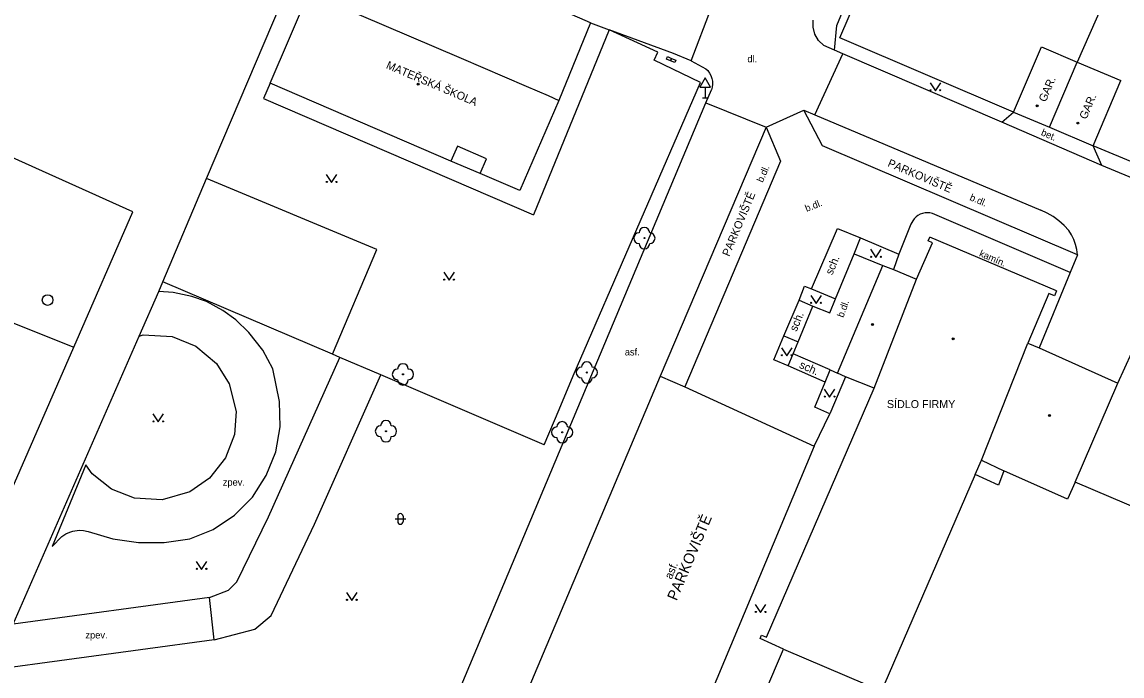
# Model space of a CAD drawing. Extents: x -596024 to -594475, y -1163820 to -1161957.
# Drawn here: x -594676 to -594573, y -1162370.7 to -1162309.5 of the extents above; entities that cross this region are included whole.
import ezdxf

# ---------------------------------------------------------------- set-up
doc = ezdxf.new("R2010")
doc.units = 0
for name, color, linetype in [('Level 10', 7, 'Continuous'), ('Level 11', 7, 'Continuous'), ('Level 22', 7, 'Continuous'), ('Level 24', 7, 'Continuous'), ('Level 27', 7, 'Continuous'), ('Level 34', 7, 'Continuous'), ('Level 36', 7, 'Continuous'), ('Level 39', 7, 'Continuous'), ('Level 40', 7, 'Continuous'), ('Level 41', 7, 'Continuous'), ('Level 5', 7, 'Continuous'), ('Level 7', 7, 'Continuous'), ('Level 8', 7, 'Continuous')]:
    doc.layers.add(name, color=color, linetype=linetype)

msp = doc.modelspace()

# ---------------------------------------------------------------- linework, layer by layer
at = {"layer": 'Level 10'}
for points in [[(-594622.76, -1162309.54), (-594647.87, -1162298.54)], [(-594600.91, -1162311.66), (-594601.39, -1162311.19), (-594601.73, -1162310.61), (-594601.9, -1162309.95), (-594601.89, -1162309.28)], [(-594613.33, -1162313.08), (-594614.98, -1162312.42), (-594621.02, -1162310.19)], [(-594599.91, -1162312.1), (-594600.91, -1162311.66)], [(-594599.12, -1162312.45), (-594599.91, -1162312.1)], [(-594613.33, -1162313.08), (-594611.96, -1162313.83)], [(-594584.21, -1162318.84), (-594599.12, -1162312.45)], [(-594611.96, -1162313.83), (-594611.78, -1162314.01), (-594611.61, -1162314.24), (-594611.49, -1162314.46), (-594611.39, -1162314.74), (-594611.34, -1162315.01), (-594611.32, -1162315.28), (-594611.35, -1162315.56), (-594611.42, -1162315.82)], [(-594611.94, -1162317.04), (-594611.42, -1162315.82)], [(-594642.05, -1162388.75), (-594611.94, -1162317.04)], [(-594606.29, -1162319.32), (-594602.76, -1162317.71)], [(-594577.13, -1162331.25), (-594601.01, -1162321.06), (-594602.76, -1162317.71)], [(-594606.29, -1162319.32), (-594604.95, -1162322.49)], [(-594574.87, -1162322.9), (-594584.21, -1162318.84)], [(-594604.95, -1162322.49), (-594613.93, -1162343.63)], [(-594539.21, -1162337.87), (-594548.12, -1162333.98), (-594574.87, -1162322.9)], [(-594577.13, -1162331.25), (-594577.82, -1162332.91)], [(-594577.82, -1162332.91), (-594580.74, -1162339.99)], [(-594613.93, -1162343.63), (-594601.79, -1162349.18)], [(-594601.79, -1162349.18), (-594613.48, -1162377.11), (-594617.98, -1162375.35)]]:
    msp.add_lwpolyline(points, dxfattribs=at)
at = {"layer": 'Level 11'}
for points in [[(-594599.91, -1162312.1), (-594599.68, -1162309.78), (-594594.58, -1162297.5), (-594588.31, -1162282.81)], [(-594687.26, -1162376.68), (-594671.17, -1162339.92), (-594665.63, -1162327.25), (-594696.11, -1162313.53), (-594685.6, -1162289.88), (-594682.8, -1162283.58)], [(-594573.15, -1162304.08), (-594577.17, -1162313.21)], [(-594613.33, -1162313.08), (-594611.41, -1162308.1)], [(-594621.02, -1162310.19), (-594628.11, -1162327.52)], [(-594601.73, -1162318.15), (-594599.12, -1162312.45)], [(-594652.78, -1162315.18), (-594653.4, -1162316.62), (-594628.11, -1162327.52)], [(-594611.94, -1162317.04), (-594606.29, -1162319.32)], [(-594602.76, -1162317.71), (-594601.73, -1162318.15)], [(-594601.73, -1162318.15), (-594580.56, -1162327.08)], [(-594584.21, -1162318.84), (-594583.12, -1162317.89)], [(-594606.29, -1162319.32), (-594616.22, -1162342.62)], [(-594574.87, -1162322.9), (-594575.66, -1162321.06)], [(-594646.93, -1162340.58), (-594642.78, -1162330.76), (-594658.72, -1162324.12)], [(-594590.73, -1162327.4), (-594590.96, -1162327.34), (-594591.19, -1162327.32), (-594591.42, -1162327.34), (-594591.65, -1162327.38), (-594591.87, -1162327.46), (-594592.08, -1162327.58), (-594592.26, -1162327.72), (-594592.43, -1162327.88), (-594592.56, -1162328.07)], [(-594577.82, -1162332.91), (-594590.73, -1162327.4)], [(-594577.13, -1162331.25), (-594577.2, -1162330.77), (-594577.31, -1162330.3), (-594577.48, -1162329.84), (-594577.69, -1162329.4), (-594577.94, -1162328.98), (-594578.39, -1162328.51), (-594578.88, -1162328.08), (-594579.41, -1162327.69), (-594579.97, -1162327.36), (-594580.56, -1162327.08)], [(-594592.76, -1162328.39), (-594593.86, -1162331.19)], [(-594592.56, -1162328.07), (-594592.76, -1162328.39)], [(-594602.06, -1162334.46), (-594599.61, -1162328.79), (-594597.47, -1162329.68)], [(-594598.07, -1162331.16), (-594597.47, -1162329.68)], [(-594597.47, -1162329.68), (-594593.86, -1162331.19)], [(-594599.81, -1162335.4), (-594598.07, -1162331.16)], [(-594598.07, -1162331.16), (-594595.37, -1162332.25)], [(-594593.86, -1162331.19), (-594594.38, -1162332.65)], [(-594652.53, -1162341.95), (-594653.47, -1162340.19), (-594654.76, -1162338.55), (-594656, -1162337.36), (-594657.22, -1162336.49), (-594658.75, -1162335.65), (-594660.1, -1162335.17), (-594661.86, -1162334.8), (-594663.21, -1162334.69)], [(-594603.22, -1162335.52), (-594602.7, -1162334.2), (-594602.06, -1162334.46)], [(-594602.06, -1162334.46), (-594599.81, -1162335.4)], [(-594604.64, -1162338.85), (-594603.22, -1162335.52)], [(-594603.31, -1162339.41), (-594601.92, -1162336.07), (-594600.35, -1162336.71), (-594599.81, -1162335.4)], [(-594603.22, -1162335.52), (-594601.92, -1162336.07)], [(-594677.49, -1162337.37), (-594671.17, -1162339.92)], [(-594664.67, -1162338.77), (-594661.94, -1162338.92), (-594659.74, -1162339.81), (-594657.81, -1162341.43), (-594656.6, -1162343.35), (-594655.96, -1162345.95), (-594656.11, -1162348.09), (-594656.94, -1162350.28), (-594658.45, -1162352.2), (-594660.31, -1162353.47), (-594662.88, -1162354.22), (-594665.48, -1162354.07), (-594667.64, -1162353.22), (-594669.44, -1162351.78), (-594670.03, -1162350.95)], [(-594665.04, -1162338.87), (-594664.67, -1162338.77)], [(-594604.23, -1162341.67), (-594605.58, -1162341.11), (-594604.64, -1162338.85)], [(-594604.64, -1162338.85), (-594603.31, -1162339.41)], [(-594600.32, -1162342.05), (-594603.77, -1162340.53), (-594603.31, -1162339.41)], [(-594658.45, -1162363.35), (-594656.66, -1162362.68), (-594655.9, -1162361.91), (-594652.94, -1162355.82), (-594646.25, -1162340.87)], [(-594604.23, -1162341.67), (-594603.77, -1162340.53)], [(-594660.31, -1162357.88), (-594658.1, -1162356.98), (-594656.12, -1162355.65), (-594654.44, -1162353.95), (-594653.13, -1162351.95), (-594652.25, -1162349.73), (-594651.83, -1162347.38), (-594651.89, -1162345), (-594652.53, -1162341.95)], [(-594600.76, -1162343.19), (-594604.23, -1162341.67)], [(-594600.34, -1162346.17), (-594601.74, -1162345.54), (-594600.76, -1162343.19), (-594600.32, -1162342.05)], [(-594600.32, -1162342.05), (-594599.63, -1162342.34)], [(-594658.03, -1162367.34), (-594654.21, -1162366.32), (-594652.68, -1162365.05), (-594648.62, -1162356.49), (-594642.39, -1162342.52)], [(-594616.22, -1162342.62), (-594629.13, -1162373.21)], [(-594616.22, -1162342.62), (-594613.93, -1162343.63)], [(-594598.88, -1162342.69), (-594600.34, -1162346.17)], [(-594601.79, -1162349.18), (-594600.34, -1162346.17)], [(-594670.03, -1162350.95), (-594673.18, -1162358.58)], [(-594586.14, -1162350.51), (-594584.04, -1162351.49)], [(-594673.18, -1162358.58), (-594672.28, -1162357.64), (-594671.92, -1162357.41), (-594671.53, -1162357.23), (-594671.26, -1162357.15), (-594670.68, -1162357.07), (-594670.25, -1162357.09), (-594669.83, -1162357.18)], [(-594669.83, -1162357.18), (-594667.51, -1162357.86), (-594665.12, -1162358.21), (-594662.7, -1162358.22), (-594660.31, -1162357.88)], [(-594658.45, -1162363.35), (-594676.86, -1162365.85)], [(-594658.03, -1162367.34), (-594658.45, -1162363.35)], [(-594658.03, -1162367.34), (-594678.74, -1162370.15)]]:
    msp.add_lwpolyline(points, dxfattribs=at)
at = {"layer": 'Level 22'}
for centre in [(-594617.71, -1162329.7), (-594640.33, -1162342.46), (-594623.1, -1162342.29), (-594641.92, -1162347.79), (-594625.41, -1162347.89)]:
    msp.add_circle(centre, 0.05, dxfattribs=at)
for centre, start, end in [((-594618.21, -1162329.7), 90, 270), ((-594617.71, -1162329.2), 0, 180), ((-594617.21, -1162329.7), 270, 90), ((-594617.71, -1162330.2), 180, 0), ((-594640.83, -1162342.46), 90, 270), ((-594640.33, -1162341.96), 0, 180), ((-594639.83, -1162342.46), 270, 90), ((-594623.6, -1162342.29), 90, 270), ((-594623.1, -1162341.79), 0, 180), ((-594622.6, -1162342.29), 270, 90), ((-594640.33, -1162342.96), 180, 0), ((-594623.1, -1162342.79), 180, 0), ((-594641.92, -1162347.29), 0, 180), ((-594625.41, -1162347.39), 0, 180), ((-594642.42, -1162347.79), 90, 270), ((-594641.42, -1162347.79), 270, 90), ((-594625.91, -1162347.89), 90, 270), ((-594624.91, -1162347.89), 270, 90), ((-594641.92, -1162348.29), 180, 0), ((-594625.41, -1162348.39), 180, 0)]:
    msp.add_arc(centre, 0.5, start, end, dxfattribs=at)
at = {"layer": 'Level 24'}
for points in [[(-594615.56, -1162312.7), (-594615.18, -1162312.86), (-594615.27, -1162313.1), (-594615.65, -1162312.94), (-594615.56, -1162312.7)], [(-594615.18, -1162312.86), (-594614.76, -1162313.03), (-594614.86, -1162313.26), (-594615.27, -1162313.1), (-594615.18, -1162312.86)]]:
    msp.add_lwpolyline(points, dxfattribs=at)
at = {"layer": 'Level 27'}
msp.add_circle((-594673.62, -1162335.5), 0.5, dxfattribs=at)
at = {"layer": 'Level 34'}
for p, q in [((-594612.03, -1162315.55), (-594612.03, -1162316.57)), ((-594612.28, -1162316.57), (-594611.78, -1162316.57))]:
    msp.add_line(p, q, dxfattribs=at)
msp.add_lwpolyline([(-594612.53, -1162315.55), (-594611.53, -1162315.55), (-594612.03, -1162314.69)], close=True, dxfattribs=at)
at = {"layer": 'Level 36'}
for p, q in [((-594641.07, -1162356), (-594640.07, -1162356)), ((-594640.82, -1162355.75), (-594640.82, -1162356.25)), ((-594640.32, -1162355.75), (-594640.32, -1162356.25))]:
    msp.add_line(p, q, dxfattribs=at)
for points in [[(-594590.95, -1162315.15), (-594590.45, -1162315.9), (-594589.95, -1162315.15)], [(-594647.51, -1162323.74), (-594647.01, -1162324.49), (-594646.51, -1162323.74)], [(-594596.52, -1162330.75), (-594596.02, -1162331.5), (-594595.52, -1162330.75)], [(-594636.51, -1162332.89), (-594636.01, -1162333.64), (-594635.51, -1162332.89)], [(-594602.13, -1162335.06), (-594601.63, -1162335.81), (-594601.13, -1162335.06)], [(-594604.88, -1162339.97), (-594604.38, -1162340.72), (-594603.88, -1162339.97)], [(-594600.86, -1162343.84), (-594600.36, -1162344.59), (-594599.86, -1162343.84)], [(-594663.75, -1162346.17), (-594663.25, -1162346.92), (-594662.75, -1162346.17)], [(-594659.7, -1162359.98), (-594659.2, -1162360.73), (-594658.7, -1162359.98)], [(-594645.62, -1162362.88), (-594645.12, -1162363.63), (-594644.62, -1162362.88)], [(-594607.32, -1162364.02), (-594606.82, -1162364.77), (-594606.32, -1162364.02)]]:
    msp.add_lwpolyline(points, dxfattribs=at)
for centre in [(-594590.9, -1162315.85), (-594590, -1162315.85), (-594647.46, -1162324.44), (-594646.56, -1162324.44), (-594596.47, -1162331.45), (-594595.57, -1162331.45), (-594636.46, -1162333.59), (-594635.56, -1162333.59), (-594602.08, -1162335.76), (-594601.18, -1162335.76), (-594604.83, -1162340.67), (-594603.93, -1162340.67), (-594600.81, -1162344.54), (-594599.91, -1162344.54), (-594663.7, -1162346.87), (-594662.8, -1162346.87), (-594659.65, -1162360.68), (-594658.75, -1162360.68), (-594645.57, -1162363.58), (-594644.67, -1162363.58), (-594607.27, -1162364.72), (-594606.37, -1162364.72)]:
    msp.add_circle(centre, 0.05, dxfattribs=at)
for centre, start, end in [((-594640.57, -1162355.75), 0, 180), ((-594640.57, -1162356.25), 180, 0)]:
    msp.add_arc(centre, 0.25, start, end, dxfattribs=at)
at = {"layer": 'Level 39'}
for centre, radius in [((-594638.91, -1162315.27), 0.09), ((-594638.91, -1162315.27), 0.0398), ((-594580.92, -1162317.3), 0.09), ((-594580.92, -1162317.3), 0.0398), ((-594577.11, -1162318.92), 0.09), ((-594577.11, -1162318.92), 0.0398), ((-594596.34, -1162337.79), 0.09), ((-594596.34, -1162337.79), 0.0398), ((-594588.78, -1162339.14), 0.09), ((-594588.78, -1162339.14), 0.0398), ((-594579.77, -1162346.31), 0.09), ((-594579.77, -1162346.31), 0.0398)]:
    msp.add_circle(centre, radius, dxfattribs=at)
at = {"layer": 'Level 5'}
for points in [[(-594652.78, -1162315.18), (-594649.14, -1162306.71)], [(-594649.14, -1162306.71), (-594634.89, -1162312.85)], [(-594583.12, -1162317.89), (-594580.52, -1162311.78)], [(-594580.52, -1162311.78), (-594577.17, -1162313.21)], [(-594634.89, -1162312.85), (-594628.79, -1162315.47)], [(-594579.76, -1162319.32), (-594577.17, -1162313.21)], [(-594577.17, -1162313.21), (-594573.06, -1162314.95)], [(-594635.83, -1162322.48), (-594652.78, -1162315.18)], [(-594575.66, -1162321.06), (-594573.06, -1162314.95)], [(-594628.79, -1162315.47), (-594626.74, -1162316.33)], [(-594625.73, -1162316.8), (-594629.39, -1162325.25)], [(-594626.74, -1162316.33), (-594625.73, -1162316.8)], [(-594583.12, -1162317.89), (-594579.76, -1162319.32)], [(-594579.76, -1162319.32), (-594575.66, -1162321.06)], [(-594635.23, -1162321.08), (-594635.83, -1162322.48)], [(-594632.49, -1162322.26), (-594635.23, -1162321.08)], [(-594633.09, -1162323.66), (-594635.83, -1162322.48)], [(-594633.09, -1162323.66), (-594632.49, -1162322.26)], [(-594629.39, -1162325.25), (-594633.09, -1162323.66)], [(-594591.12, -1162329.96), (-594590.96, -1162329.6)], [(-594579.09, -1162334.65), (-594590.96, -1162329.6)], [(-594592.23, -1162333.53), (-594590.73, -1162330.13)], [(-594590.73, -1162330.13), (-594591.12, -1162329.96)], [(-594599.63, -1162342.34), (-594595.37, -1162332.25)], [(-594595.37, -1162332.25), (-594594.38, -1162332.65), (-594592.23, -1162333.53)], [(-594596.19, -1162343.77), (-594592.23, -1162333.53)], [(-594579.09, -1162334.65), (-594579.29, -1162335.11)], [(-594579.81, -1162334.89), (-594581.78, -1162339.53)], [(-594579.29, -1162335.11), (-594579.81, -1162334.89)], [(-594586.14, -1162350.51), (-594581.78, -1162339.53)], [(-594581.78, -1162339.53), (-594580.74, -1162339.99)], [(-594580.74, -1162339.99), (-594573.35, -1162343.29)], [(-594573.35, -1162343.29), (-594572.06, -1162340.42)], [(-594598.88, -1162342.69), (-594599.63, -1162342.34)], [(-594596.19, -1162343.77), (-594598.88, -1162342.69)], [(-594606.28, -1162367.08), (-594596.19, -1162343.77)], [(-594577.36, -1162352.56), (-594573.35, -1162343.29)], [(-594586.71, -1162351.83), (-594586.14, -1162350.51)], [(-594586.71, -1162351.83), (-594595.29, -1162371.62)], [(-594584.53, -1162352.85), (-594586.71, -1162351.83)], [(-594584.04, -1162351.49), (-594584.53, -1162352.85)], [(-594578.07, -1162354.16), (-594584.04, -1162351.49)], [(-594577.36, -1162352.56), (-594578.07, -1162354.16)], [(-594559.45, -1162360.17), (-594577.36, -1162352.56)], [(-594606.87, -1162367.21), (-594606.73, -1162366.89)], [(-594604.68, -1162368.21), (-594606.87, -1162367.21)], [(-594606.73, -1162366.89), (-594606.28, -1162367.08)], [(-594614.28, -1162390.66), (-594611.96, -1162385.23), (-594604.68, -1162368.21)], [(-594604.68, -1162368.21), (-594594.94, -1162372.34)]]:
    msp.add_lwpolyline(points, dxfattribs=at)
at = {"layer": 'Level 7'}
for points in [[(-594599.41, -1162310.94), (-594592.79, -1162295.56), (-594585.58, -1162277.89)], [(-594627.09, -1162349.06), (-594642.39, -1162342.52), (-594646.25, -1162340.87), (-594646.93, -1162340.58), (-594662.82, -1162333.79), (-594658.72, -1162324.12), (-594650.98, -1162305.9)], [(-594622.76, -1162309.54), (-594625.73, -1162316.8)], [(-594616.44, -1162312.29), (-594621.02, -1162310.19)], [(-594583.12, -1162317.89), (-594599.41, -1162310.94)], [(-594624.39, -1162342.61), (-594612.46, -1162315.11), (-594616.8, -1162313.03), (-594616.44, -1162312.29)], [(-594554.27, -1162329.95), (-594575.66, -1162321.06)], [(-594678.74, -1162370.15), (-594676.86, -1162365.85), (-594665.04, -1162338.87), (-594663.21, -1162334.69), (-594662.82, -1162333.79)], [(-594627.09, -1162349.06), (-594625.7, -1162345.76)]]:
    msp.add_lwpolyline(points, dxfattribs=at)
at = {"layer": 'Level 8'}
for points in [[(-594622.76, -1162309.54), (-594621.02, -1162310.19)], [(-594625.7, -1162345.76), (-594624.39, -1162342.61)]]:
    msp.add_lwpolyline(points, dxfattribs=at)

# ---------------------------------------------------------------- texts
at = {"layer": 'Level 40'}
for s, p in [('dl.', (-594608.06, -1162313.23)), ('asf.', (-594619.55, -1162340.69)), ('zpev.', (-594657.21, -1162352.89)), ('zpev.', (-594670.08, -1162367.2))]:
    msp.add_text(s, height=0.65, dxfattribs=at).set_placement(p)
for s, height, rotation, p in [('bet.', 0.65, 336.45, (-594580.61, -1162320.03)), ('b.dl.', 0.65, 66.5, (-594606.62, -1162324.54)), ('b.dl.', 0.65, 336.79, (-594587.29, -1162326.12)), ('b.dl.', 0.65, 21.63, (-594602.51, -1162327.25)), ('sch.', 0.75, 67.35, (-594600.11, -1162333.21)), ('kamín.', 0.65, 336.79, (-594586.4, -1162331.37)), ('b.dl.', 0.65, 70.27, (-594599.07, -1162337.19)), ('sch.', 0.75, 67.35, (-594603.46, -1162338.5)), ('sch.', 0.75, 336.34, (-594603.26, -1162341.83)), ('asf.', 0.75, 67, (-594615.17, -1162361.71))]:
    msp.add_text(s, height=height, rotation=rotation, dxfattribs=at).set_placement(p)
at = {"layer": 'Level 41'}
for s, height, rotation, p in [('MATEŘSKÁ ŠKOLA', 0.75, 337, (-594641.97, -1162313.77)), ('GAR.', 0.75, 66.81, (-594580.12, -1162317.01)), ('GAR.', 0.75, 66.81, (-594576.31, -1162318.63)), (' PARKOVIŠTĚ', 0.75, 336.79, (-594595.24, -1162322.84)), (' PARKOVIŠTĚ', 0.75, 67.32, (-594609.87, -1162331.73)), (' PARKOVIŠTĚ', 1, 67, (-594614.84, -1162364.07))]:
    msp.add_text(s, height=height, rotation=rotation, dxfattribs=at).set_placement(p)
msp.add_text('SÍDLO FIRMY', height=0.75, dxfattribs=at).set_placement((-594594.99, -1162345.62))

doc.saveas('drawing.dxf')
